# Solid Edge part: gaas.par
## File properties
Title: gaas
Author: Stella-Marii
Template: iso metric part.par
Last saved by: Stella-Marii
Revision: 8
Application: Solid Edge
Document Number: 15
Density: 1024,000 kg/m^3
Accuracy: 0,990
Username: Stella-Marii
Material: ABS Plastic, high impact
Face Style: Red
Fill Style: ANSI34(Plastic)
Virtual Style: Red (Shiny)
Grouping: Non-metals\Plastics
LibraryName: Materials
Coef. of Thermal Exp: 9e-05
Thermal Conductivity: 0.2
Specific Heat: 0.0
Modulus of Elasticity: 1378951400.0
Poisson's Ratio: 0.4
Yield Stress: 31026406.5
Ultimate Stress: 0.0
Elongation: 0.0
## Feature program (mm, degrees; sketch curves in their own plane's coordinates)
sketch for "unnamed Protrusion 1" plane through (0, 0, 0) normal (1, 0, 0) x-axis (0, 1, 0)
  circle centre (0, 0) radius 20
extrude "unnamed Protrusion 1" add finite 30 along +normal
sketch for "ExtrudedProtrusion_2" plane through (0, 0, 0) normal (0, 0, 1) x-axis (1, 0, 0)
  line (0, 0) -> (0, 0)
  line (0, 0) -> (0, 0)
  arc centre (16.8102, -26.6809) radius 18.0891 from (24.738, -42.9403) to (0, -20) cw
  arc centre (21.9261, -37.1732) radius 6.4161 from (26.3706, -41.8005) to (24.738, -42.9403) cw
  line (37.4617, -31.1474) -> (26.3706, -41.8005)
  line (30, -20) -> (37.4617, -31.1474)
  line (30, 0) -> (30, -20)
  line (0, 0) -> (30, 0)
  line (0, 0) -> (0, -20)
extrude "ExtrudedProtrusion_2" add finite 5 symmetric
fillet "Round_1" radius 4  Radii2 = 7 mm
fillet "Round_2" radius 1
fillet "Round_3" radius 1
sketch for "ExtrudedCutout_1" plane through (0, -0.5126, 0) normal (-1, 0, 0) x-axis (0, 0, 1)
  circle centre (0, 0.5126) radius 12.5
extrude "ExtrudedCutout_1" cut finite 761.7104 along -normal
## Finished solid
Body 1: solid body, 36 faces, 81 edges, 46 vertices.
  Faces by surface: torus 14, cylinder 12, plane 6, blend 4
  Edges by curve: circle 50, line 19, intersection 12
Bounding box of the edges (mm; curved faces can reach further): 36.659 x 64.770 x 40.000, from (-1.279, -44.7701, -20) to (35.3802, 20, 20).
Cylindrical faces by radius (mm): R1 x6, R4 x1, R6.4161 x1, R7 x1, R12.5 x1, R18.0891 x1, R20 x1
Toroidal faces (ring radius, tube radius in mm): R2 r1 x4, R5 r1 x2, R5.4161 r1 x2, R6 r1 x2, R17.0891 r1 x2, R19 r1 x2
Planar faces by outward normal: +x 1, +z 1, -x 1, -z 1, oblique 2
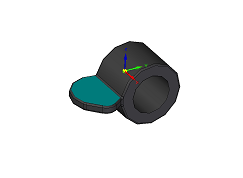
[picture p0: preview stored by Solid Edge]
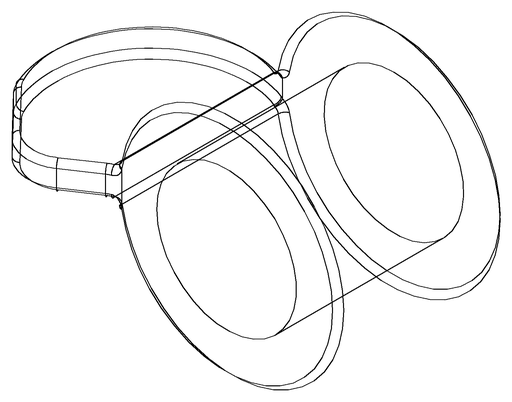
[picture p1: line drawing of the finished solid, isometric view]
